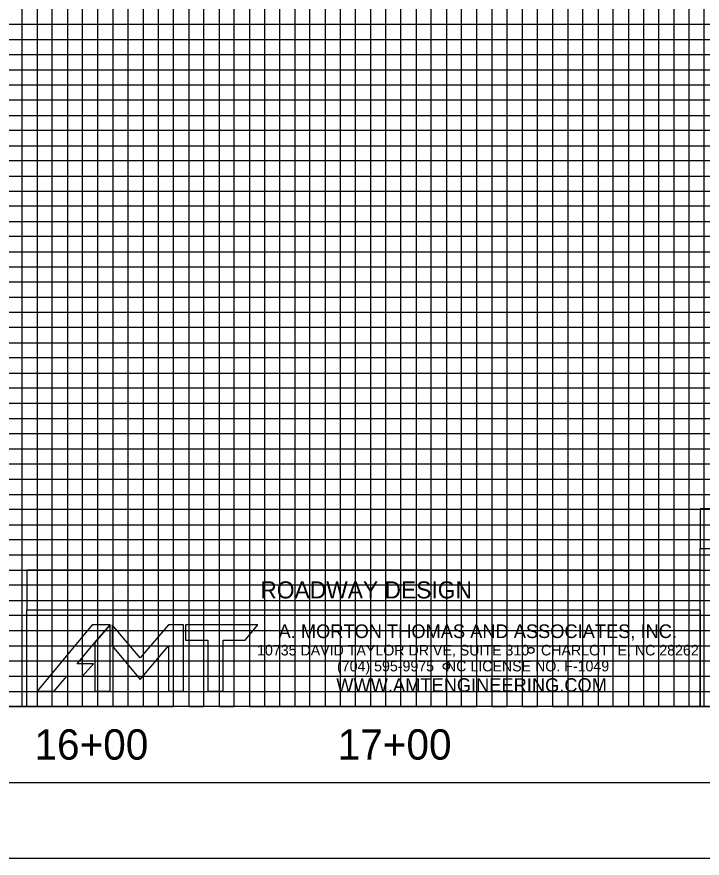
# Model space of a CAD drawing. Extents: x 1524869 to 1526553, y 501099 to 502199.
# Drawn here: x 1526209.4 to 1526435.4, y 501098.6 to 501376.1 of the extents above; entities that cross this region are included whole.
import ezdxf

# ---------------------------------------------------------------- set-up
doc = ezdxf.new("R2010")
doc.units = 0
for name, color, linetype in [('Exist Vertical Profile Horizontal Axis Label Major', 7, 'Continuous'), ('Prop Grid Mask', 7, 'Continuous'), ('Prop Horizontal Alignment Curve and Spiral Data', 7, 'Continuous'), ('Sheet Block Title CELL', 7, 'Continuous'), ('Sheet Layout Profile Border Port 1', 7, 'Continuous'), ('Sheet Plot Border Outside CELL', 7, 'Continuous'), ('Sheet Profile CELL', 7, 'Continuous'), ('Sheet Profile Grid Major CELL', 7, 'Continuous'), ('Sheet Profile Grid Middle CELL', 7, 'Continuous'), ('Sheet Profile Grid Minor CELL', 7, 'Continuous')]:
    doc.layers.add(name, color=color, linetype=linetype)

msp = doc.modelspace()

# ---------------------------------------------------------------- linework, layer by layer
at = {"layer": 'Prop Grid Mask'}
for points in [[(1526434.75, 501200.68), (1526536.08, 501200.68), (1526536.08, 501213.73), (1526434.75, 501213.73)], [(1526434.75, 501200.68), (1526536.08, 501200.68), (1526536.08, 501148.56), (1526434.75, 501148.56)], [(1526212.71, 501180.52), (1526434.75, 501180.52), (1526434.75, 501193.56), (1526212.71, 501193.56)], [(1526212.71, 501180.52), (1526434.75, 501180.52), (1526434.75, 501148.56), (1526212.71, 501148.56)]]:
    msp.add_lwpolyline(points, close=True, dxfattribs=at)
at = {"layer": 'Sheet Block Title CELL'}
msp.add_lwpolyline([(1526212.71, 501180.52), (1526434.75, 501180.52), (1526434.75, 501148.56), (1526212.71, 501148.56)], close=True, dxfattribs=at)
for points in [[(1526235.14, 501169.66), (1526240.17, 501175.56), (1526234.29, 501175.56), (1526216.06, 501153.6), (1526221.76, 501153.6), (1526225.85, 501158.54), (1526231.07, 501158.54), (1526234.65, 501162.69), (1526229.26, 501162.69), (1526235.14, 501169.66)], [(1526240.17, 501153.6), (1526240.17, 501175.56), (1526235.14, 501169.66), (1526235.14, 501153.6), (1526240.17, 501153.6)], [(1526250.04, 501157.47), (1526259.37, 501168.59), (1526259.37, 501153.6), (1526264.4, 501153.6), (1526264.4, 501175.56), (1526259.37, 501175.56), (1526250.04, 501164.6), (1526240.82, 501175.56), (1526240.82, 501168.57), (1526250.04, 501157.47)], [(1526277.43, 501153.6), (1526277.43, 501170.52), (1526284.73, 501170.52), (1526288.93, 501175.56), (1526265.05, 501175.56), (1526265.05, 501170.52), (1526272.4, 501170.52), (1526272.4, 501153.6), (1526277.43, 501153.6)]]:
    msp.add_lwpolyline(points, dxfattribs=at)
for centre in [(1526378.94, 501167.08), (1526351.02, 501161.86)]:
    msp.add_circle(centre, 1, dxfattribs=at)
at = {"layer": 'Sheet Layout Profile Border Port 1'}
msp.add_lwpolyline([(1525536.08, 501648.56), (1526486.08, 501648.56), (1526486.08, 501148.56), (1525536.08, 501148.56)], close=True, dxfattribs=at)
at = {"layer": 'Sheet Plot Border Outside CELL'}
msp.add_lwpolyline([(1524869.08, 501098.56), (1526553.08, 501098.56), (1526553.08, 502198.56), (1524869.08, 502198.56)], close=True, dxfattribs=at)
at = {"layer": 'Sheet Profile CELL'}
for p, q in [((1526536.08, 501148.56), (1525036.08, 501148.56)), ((1525036.08, 501123.56), (1526536.08, 501123.56))]:
    msp.add_line(p, q, dxfattribs=at)
msp.add_lwpolyline([(1526536.08, 502173.56), (1525036.08, 502173.56), (1525036.08, 501123.56), (1526536.08, 501123.56)], close=True, dxfattribs=at)
at = {"layer": 'Sheet Profile Grid Major CELL'}
for points in [[(1525986.08, 501148.56), (1526036.08, 501148.56), (1526036.08, 501648.56), (1526086.08, 501648.56), (1526086.08, 501148.56), (1526136.08, 501148.56), (1526136.08, 501648.56), (1526186.08, 501648.56), (1526186.08, 501148.56), (1526236.08, 501148.56), (1526236.08, 501648.56), (1526286.08, 501648.56), (1526286.08, 501148.56), (1526336.08, 501148.56), (1526336.08, 501648.56), (1526386.08, 501648.56), (1526386.08, 501148.56), (1526436.08, 501148.56), (1526436.08, 501148.56), (1526436.08, 501648.56), (1526486.08, 501648.56), (1526486.08, 501148.56)], [(1526536.08, 501348.56), (1525036.08, 501348.56), (1525036.08, 501298.56), (1526536.08, 501298.56)], [(1526536.08, 501248.56), (1525036.08, 501248.56), (1525036.08, 501248.56), (1525036.08, 501198.56), (1526536.08, 501198.56)], [(1526536.08, 501148.56), (1525036.08, 501148.56)]]:
    msp.add_lwpolyline(points, dxfattribs=at)
at = {"layer": 'Sheet Profile Grid Middle CELL'}
for points in [[(1526011.08, 501148.56), (1526061.08, 501148.56), (1526061.08, 501648.56), (1526111.08, 501648.56), (1526111.08, 501148.56), (1526161.08, 501148.56), (1526161.08, 501648.56), (1526211.08, 501648.56), (1526211.08, 501148.56), (1526261.08, 501148.56), (1526261.08, 501648.56), (1526311.08, 501648.56), (1526311.08, 501148.56), (1526361.08, 501148.56), (1526361.08, 501648.56), (1526411.08, 501648.56), (1526411.08, 501148.56), (1526461.08, 501148.56), (1526461.08, 501648.56)], [(1526536.08, 501373.56), (1525036.08, 501373.56), (1525036.08, 501323.56), (1526536.08, 501323.56)], [(1526536.08, 501273.56), (1525036.08, 501273.56), (1525036.08, 501223.56), (1526536.08, 501223.56)], [(1526536.08, 501173.56), (1525036.08, 501173.56)]]:
    msp.add_lwpolyline(points, dxfattribs=at)
at = {"layer": 'Sheet Profile Grid Minor CELL'}
for p, q in [((1526036.08, 501368.56), (1526486.08, 501368.56)), ((1526486.08, 501363.56), (1526036.08, 501363.56)), ((1526036.08, 501358.56), (1526486.08, 501358.56)), ((1526486.08, 501353.56), (1526036.08, 501353.56)), ((1526036.08, 501343.56), (1526486.08, 501343.56)), ((1526486.08, 501338.56), (1526036.08, 501338.56)), ((1526036.08, 501333.56), (1526486.08, 501333.56)), ((1526486.08, 501328.56), (1526036.08, 501328.56)), ((1526036.08, 501318.56), (1526486.08, 501318.56)), ((1526486.08, 501313.56), (1526036.08, 501313.56)), ((1526036.08, 501308.56), (1526486.08, 501308.56)), ((1526486.08, 501303.56), (1526036.08, 501303.56)), ((1526036.08, 501293.56), (1526486.08, 501293.56)), ((1526486.08, 501288.56), (1526036.08, 501288.56)), ((1526036.08, 501283.56), (1526486.08, 501283.56)), ((1526486.08, 501278.56), (1526036.08, 501278.56)), ((1526036.08, 501268.56), (1526486.08, 501268.56)), ((1526486.08, 501263.56), (1526036.08, 501263.56)), ((1526036.08, 501258.56), (1526486.08, 501258.56)), ((1526486.08, 501253.56), (1526036.08, 501253.56)), ((1526036.08, 501243.56), (1526486.08, 501243.56)), ((1526486.08, 501238.56), (1526036.08, 501238.56)), ((1526036.08, 501233.56), (1526486.08, 501233.56)), ((1526486.08, 501228.56), (1526036.08, 501228.56)), ((1526036.08, 501218.56), (1526486.08, 501218.56)), ((1526486.08, 501213.56), (1526036.08, 501213.56)), ((1526036.08, 501208.56), (1526486.08, 501208.56)), ((1526486.08, 501203.56), (1526036.08, 501203.56)), ((1526036.08, 501193.56), (1526486.08, 501193.56)), ((1526486.08, 501188.56), (1526036.08, 501188.56)), ((1526036.08, 501183.56), (1526486.08, 501183.56)), ((1526486.08, 501178.56), (1526036.08, 501178.56)), ((1526036.08, 501168.56), (1526486.08, 501168.56)), ((1526486.08, 501163.56), (1526036.08, 501163.56)), ((1526036.08, 501158.56), (1526486.08, 501158.56)), ((1526036.08, 501153.56), (1526486.08, 501153.56))]:
    msp.add_line(p, q, dxfattribs=at)
for points in [[(1526216.08, 501648.56), (1526216.08, 501148.56), (1526221.08, 501148.56), (1526221.08, 501648.56)], [(1526226.08, 501148.56), (1526231.08, 501148.56), (1526231.08, 501648.56)], [(1526226.08, 501648.56), (1526226.08, 501148.56)], [(1526241.08, 501648.56), (1526241.08, 501148.56), (1526246.08, 501148.56), (1526246.08, 501648.56)], [(1526251.08, 501648.56), (1526251.08, 501148.56), (1526256.08, 501148.56), (1526256.08, 501648.56)], [(1526266.08, 501648.56), (1526266.08, 501148.56), (1526271.08, 501148.56), (1526271.08, 501648.56)], [(1526276.08, 501648.56), (1526276.08, 501148.56), (1526281.08, 501148.56), (1526281.08, 501648.56)], [(1526291.08, 501648.56), (1526291.08, 501148.56), (1526296.08, 501148.56), (1526296.08, 501648.56)], [(1526301.08, 501648.56), (1526301.08, 501148.56), (1526306.08, 501148.56), (1526306.08, 501648.56)], [(1526316.08, 501648.56), (1526316.08, 501148.56), (1526321.08, 501148.56), (1526321.08, 501648.56)], [(1526326.08, 501648.56), (1526326.08, 501148.56), (1526331.08, 501148.56), (1526331.08, 501648.56)], [(1526341.08, 501648.56), (1526341.08, 501148.56), (1526346.08, 501148.56), (1526346.08, 501648.56)], [(1526351.08, 501648.56), (1526351.08, 501148.56), (1526356.08, 501148.56), (1526356.08, 501648.56)], [(1526366.08, 501648.56), (1526366.08, 501148.56), (1526371.08, 501148.56), (1526371.08, 501648.56)], [(1526376.08, 501648.56), (1526376.08, 501148.56), (1526381.08, 501148.56), (1526381.08, 501648.56)], [(1526391.08, 501648.56), (1526391.08, 501148.56), (1526396.08, 501148.56), (1526396.08, 501648.56)], [(1526401.08, 501648.56), (1526401.08, 501148.56), (1526406.08, 501148.56), (1526406.08, 501648.56)], [(1526416.08, 501648.56), (1526416.08, 501148.56), (1526421.08, 501148.56), (1526421.08, 501648.56)], [(1526426.08, 501648.56), (1526426.08, 501148.56), (1526431.08, 501148.56), (1526431.08, 501648.56)]]:
    msp.add_lwpolyline(points, dxfattribs=at)

# ---------------------------------------------------------------- texts
at = {"layer": 'Exist Vertical Profile Horizontal Axis Label Major'}
for s, p in [('16+00', (1526215.21, 501131.06)), ('17+00', (1526315.21, 501131.06))]:
    msp.add_text(s, height=10, dxfattribs=at).set_placement(p)
at = {"layer": 'Prop Horizontal Alignment Curve and Spiral Data'}
msp.add_text('ROADWAY DESIGN', height=5.625, rotation=360, dxfattribs=at).set_placement((1526289.7, 501184.23))
at = {"layer": 'Sheet Block Title CELL'}
for s, height, p in [('A. MORTON THOMAS AND ASSOCIATES, INC.', 4.5, (1526295.72, 501171.17)), ('10735 DAVID TAYLOR DRIVE, SUITE 310   CHARLOTTE, NC 28262', 3.5, (1526288.62, 501165.42)), ('(704) 595-9975   NC LICENSE NO. F-1049', 3.5, (1526315, 501160.17)), ('WWW.AMTENGINEERING.COM', 4.5, (1526314.74, 501153.42))]:
    msp.add_text(s, height=height, rotation=359.9995, dxfattribs=at).set_placement(p)

doc.saveas('drawing.dxf')
